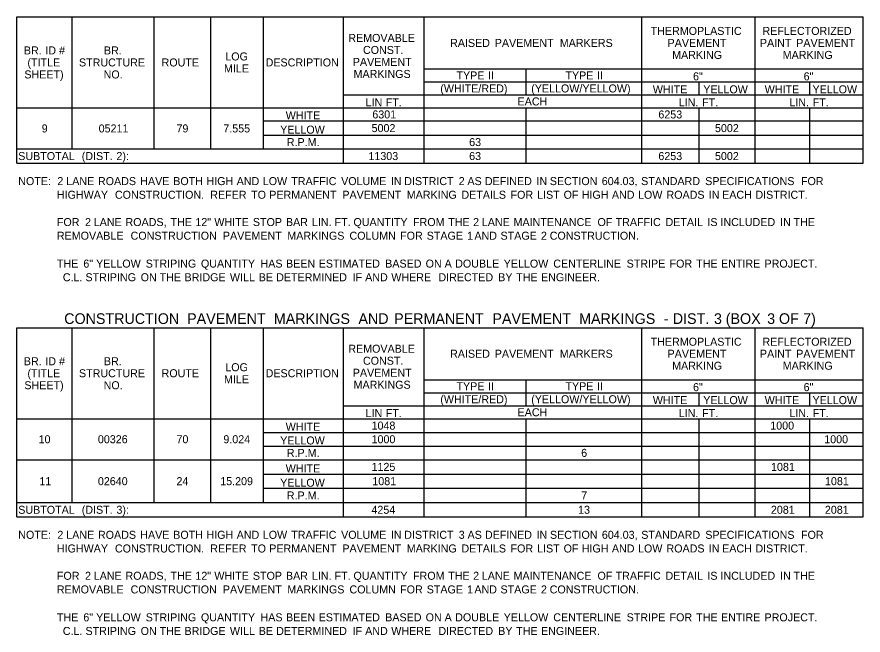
# Model space of a CAD drawing. Extents: x 544255 to 1930787, y -1947044 to 596640.
# Drawn here: x 544255 to 544890, y -1946993 to -1946529 of the extents above; entities that cross this region are included whole.
import ezdxf

# ---------------------------------------------------------------- set-up
doc = ezdxf.new("R2010")
doc.units = 0
doc.layers.add('Default', color=7, linetype='Continuous')

msp = doc.modelspace()

# ---------------------------------------------------------------- linework, layer by layer
at = {"layer": 'Default'}
for p, q in [((544255.45, -1946529.42), (544889.69, -1946529.42)), ((544255.45, -1946529.42), (544560.63, -1946529.42)), ((544255.45, -1946639.1), (544255.45, -1946529.42)), ((544296.89, -1946628.38), (544296.89, -1946529.42)), ((544358.31, -1946628.38), (544358.31, -1946529.42)), ((544400.73, -1946628.38), (544400.73, -1946529.42)), ((544440.21, -1946628.38), (544440.21, -1946529.42)), ((544500.18, -1946639.1), (544500.18, -1946529.42)), ((544560.63, -1946639.1), (544560.63, -1946529.42)), ((544723.94, -1946639.1), (544723.94, -1946529.42)), ((544808.76, -1946597.67), (544808.76, -1946529.42)), ((544808.76, -1946639.1), (544808.76, -1946529.42)), ((544889.69, -1946639.1), (544889.69, -1946529.42)), ((544560.63, -1946568.42), (544889.69, -1946568.42)), ((544637.16, -1946587.92), (544637.16, -1946568.42)), ((544560.63, -1946578.17), (544889.69, -1946578.17)), ((544766.84, -1946587.92), (544766.84, -1946578.17)), ((544849.71, -1946587.92), (544849.71, -1946578.17)), ((544500.18, -1946587.92), (544889.69, -1946587.92)), ((544500.18, -1946597.67), (544500.18, -1946587.92)), ((544255.45, -1946597.67), (544440.21, -1946597.67)), ((544255.45, -1946597.67), (544400.73, -1946597.67)), ((544400.73, -1946597.67), (544889.69, -1946597.67)), ((544637.16, -1946639.1), (544637.16, -1946597.67)), ((544723.94, -1946597.67), (544808.76, -1946597.67)), ((544766.84, -1946639.1), (544766.84, -1946597.67)), ((544808.76, -1946597.67), (544889.69, -1946597.67)), ((544849.71, -1946639.1), (544849.71, -1946597.67)), ((544440.21, -1946607.42), (544889.69, -1946607.42)), ((544440.21, -1946618.14), (544889.69, -1946618.14)), ((544255.45, -1946628.38), (544889.69, -1946628.38)), ((544500.18, -1946639.1), (544500.18, -1946628.38)), ((544255.45, -1946639.1), (544889.69, -1946639.1)), ((544255.45, -1946762.44), (544889.69, -1946762.44)), ((544255.45, -1946762.44), (544560.63, -1946762.44)), ((544255.45, -1946904.3), (544255.45, -1946762.44)), ((544296.89, -1946893.58), (544296.89, -1946762.44)), ((544358.31, -1946893.58), (544358.31, -1946762.44)), ((544400.73, -1946893.58), (544400.73, -1946762.44)), ((544440.21, -1946893.58), (544440.21, -1946762.44)), ((544500.18, -1946904.3), (544500.18, -1946762.44)), ((544560.63, -1946904.3), (544560.63, -1946762.44)), ((544723.94, -1946904.3), (544723.94, -1946762.44)), ((544808.76, -1946830.69), (544808.76, -1946762.44)), ((544808.76, -1946904.3), (544808.76, -1946762.44)), ((544889.69, -1946904.3), (544889.69, -1946762.44)), ((544560.63, -1946801.44), (544889.69, -1946801.44)), ((544637.16, -1946820.94), (544637.16, -1946801.44)), ((544560.63, -1946811.19), (544889.69, -1946811.19)), ((544766.84, -1946820.94), (544766.84, -1946811.19)), ((544849.71, -1946820.94), (544849.71, -1946811.19)), ((544500.18, -1946820.94), (544889.69, -1946820.94)), ((544500.18, -1946830.69), (544500.18, -1946820.94)), ((544255.45, -1946830.69), (544440.21, -1946830.69)), ((544255.45, -1946830.69), (544400.73, -1946830.69)), ((544400.73, -1946830.69), (544889.69, -1946830.69)), ((544637.16, -1946904.3), (544637.16, -1946830.69)), ((544723.94, -1946830.69), (544808.76, -1946830.69)), ((544766.84, -1946904.3), (544766.84, -1946830.69)), ((544808.76, -1946830.69), (544889.69, -1946830.69)), ((544849.71, -1946904.3), (544849.71, -1946830.69)), ((544440.21, -1946840.93), (544889.69, -1946840.93)), ((544440.21, -1946851.17), (544889.69, -1946851.17)), ((544255.45, -1946861.4), (544889.69, -1946861.4)), ((544440.21, -1946872.13), (544889.69, -1946872.13)), ((544440.21, -1946882.85), (544889.69, -1946882.85)), ((544255.45, -1946893.58), (544889.69, -1946893.58)), ((544500.18, -1946904.3), (544500.18, -1946893.58)), ((544255.45, -1946904.3), (544889.69, -1946904.3))]:
    msp.add_line(p, q, dxfattribs=at)

# ---------------------------------------------------------------- texts
for s, height, p in [('THERMOPLASTIC', 6, (544730.47, -1946542.92)), ('REFLECTORIZED', 6, (544814.27, -1946542.92)), ('REMOVABLE', 6, (544503.83, -1946548.17)), ('RAISED', 6, (544580.13, -1946551.92)), (' PAVEMENT', 6, (544611.39, -1946551.92)), (' MARKERS', 6, (544660.13, -1946551.92)), ('PAVEMENT', 6, (544743.15, -1946551.92)), ('PAINT', 6, (544812.37, -1946551.92)), (' PAVEMENT', 6, (544837.35, -1946551.92)), ('BR.', 6, (544260.65, -1946557.54)), (' ID', 6, (544274.51, -1946557.54)), (' #', 6, (544284.8, -1946557.54)), ('BR.', 6, (544320.67, -1946557.54)), ('LOG', 6, (544411.64, -1946562.04)), ('CONST.', 6, (544514.85, -1946557.17)), ('MARKING', 6, (544746.58, -1946560.92)), ('MARKING', 6, (544829.45, -1946560.92)), ('(TITLE', 6, (544263.34, -1946566.54)), ('STRUCTURE', 6, (544301.96, -1946566.54)), ('ROUTE', 6, (544363.89, -1946566.54)), ('DESCRIPTION', 6, (544441.88, -1946566.54)), ('PAVEMENT', 6, (544507.2, -1946566.17)), ('SHEET)', 6, (544261.02, -1946575.54)), ('NO.', 6, (544320.44, -1946575.54)), ('MILE', 6, (544410.67, -1946571.04)), ('MARKINGS', 6, (544507.79, -1946575.17)), ('TYPE', 6, (544584.93, -1946576.29)), (' II', 6, (544606.42, -1946576.29)), ('TYPE', 6, (544666.59, -1946576.29)), (' II', 6, (544688.07, -1946576.29)), ('6"', 6, (544762.24, -1946576.97)), ('6"', 6, (544845.12, -1946576.97)), ('(WHITE/RED)', 6, (544572.8, -1946586.04)), ('(YELLOW/YELLOW)', 6, (544640.95, -1946586.04)), ('WHITE', 6, (544732.09, -1946586.72)), ('YELLOW', 6, (544769.88, -1946586.72)), ('WHITE', 6, (544815.94, -1946586.72)), ('YELLOW', 6, (544851.78, -1946586.72)), ('LIN', 6, (544516.82, -1946596.47)), (' FT.', 6, (544529.66, -1946596.47)), ('EACH', 6, (544630.73, -1946595.79)), ('LIN.', 6, (544751.56, -1946596.47)), (' FT.', 6, (544766.82, -1946596.47)), ('LIN.', 6, (544834.44, -1946596.47)), (' FT.', 6, (544849.69, -1946596.47)), ('WHITE', 6, (544456.92, -1946606.22)), ('6301', 6, (544521.85, -1946605.54)), ('6253', 6, (544736.26, -1946605.54)), ('9', 6, (544274.03, -1946616.02)), ('05211', 6, (544316.72, -1946616.02)), ('79', 6, (544375.05, -1946616.02)), ('7.555', 6, (544410.15, -1946616.02)), ('YELLOW', 6, (544452.77, -1946616.94)), ('5002', 6, (544521.3, -1946615.78)), ('5002', 6, (544778.7, -1946615.78)), ('R.P.M.', 6, (544457.75, -1946626.26)), ('63', 6, (544594.43, -1946626.26)), ('SUBTOTAL', 6, (544256.43, -1946636.74)), (' (DIST.', 6, (544301.82, -1946636.74)), (' 2):', 6, (544327.79, -1946636.74)), ('11303', 6, (544518.93, -1946636.74)), ('63', 6, (544594.42, -1946636.74)), ('6253', 6, (544736.25, -1946636.74)), ('5002', 6, (544778.69, -1946636.74)), ('NOTE:', 6, (544256.43, -1946655.51)), ('  2', 6, (544281.31, -1946655.51)), (' LANE', 6, (544290.19, -1946655.51)), (' ROADS', 6, (544313.97, -1946655.51)), (' HAVE', 6, (544345.67, -1946655.51)), (' BOTH', 6, (544370.39, -1946655.51)), (' HIGH', 6, (544395.33, -1946655.51)), (' AND', 6, (544417.94, -1946655.51)), (' LOW', 6, (544437.52, -1946655.51)), (' TRAFFIC', 6, (544458.84, -1946655.51)), (' VOLUME', 6, (544496.24, -1946655.51)), (' IN', 6, (544533.52, -1946655.51)), (' DISTRICT', 6, (544543.54, -1946655.51)), (' 2', 6, (544584.36, -1946655.51)), (' AS', 6, (544590.9, -1946655.51)), (' DEFINED', 6, (544603.98, -1946655.51)), (' IN', 6, (544642.66, -1946655.51)), (' SECTION', 6, (544652.68, -1946655.51)), (' 604.03,', 6, (544691.59, -1946655.51)), (' STANDARD', 6, (544721.13, -1946655.51)), (' SPECIFICATIONS', 6, (544769.13, -1946655.51)), (' FOR', 6, (544840.9, -1946655.51)), ('             HIGHWAY', 6, (544256.43, -1946665.75)), (' CONSTRUCTION.', 6, (544326.68, -1946665.75)), (' REFER', 6, (544398.14, -1946665.75)), (' TO', 6, (544428.77, -1946665.75)), (' PERMANENT', 6, (544442.37, -1946665.75)), (' PAVEMENT', 6, (544497.17, -1946665.75)), (' MARKING', 6, (544545.45, -1946665.75)), (' DETAILS', 6, (544586.38, -1946665.75)), (' FOR', 6, (544623.21, -1946665.75)), (' LIST', 6, (544643.13, -1946665.75)), (' OF', 6, (544662.99, -1946665.75)), (' HIGH', 6, (544676.57, -1946665.75)), (' AND', 6, (544699.18, -1946665.75)), (' LOW', 6, (544718.77, -1946665.75)), (' ROADS', 6, (544740.09, -1946665.75)), (' IN', 6, (544771.8, -1946665.75)), (' EACH', 6, (544781.82, -1946665.75)), (' DISTRICT.', 6, (544806.77, -1946665.75)), ('             FOR', 6, (544256.43, -1946686.22)), (' 2', 6, (544304.27, -1946686.22)), (' LANE', 6, (544310.82, -1946686.22)), (' ROADS,', 6, (544334.6, -1946686.22)), (' THE', 6, (544368.32, -1946686.22)), (' 12"', 6, (544386.97, -1946686.22)), (' WHITE', 6, (544401.2, -1946686.22)), (' STOP', 6, (544430.09, -1946686.22)), (' BAR', 6, (544454.88, -1946686.22)), (' LIN.', 6, (544474.34, -1946686.22)), (' FT.', 6, (544491.31, -1946686.22)), (' QUANTITY', 6, (544505.47, -1946686.22)), (' FROM', 6, (544550.13, -1946686.22)), (' THE', 6, (544576.5, -1946686.22)), (' 2', 6, (544595.15, -1946686.22)), (' LANE', 6, (544601.7, -1946686.22)), (' MAINTENANCE', 6, (544625.48, -1946686.22)), (' OF', 6, (544688.38, -1946686.22)), (' TRAFFIC', 6, (544701.97, -1946686.22)), (' DETAIL', 6, (544739.36, -1946686.22)), (' IS', 6, (544770.74, -1946686.22)), (' INCLUDED', 6, (544780.55, -1946686.22)), (' IN', 6, (544825.28, -1946686.22)), (' THE', 6, (544835.31, -1946686.22)), ('             REMOVABLE', 6, (544256.43, -1946696.46)), (' CONSTRUCTION', 6, (544338.42, -1946696.46)), (' PAVEMENT', 6, (544407.6, -1946696.46)), (' MARKINGS', 6, (544455.89, -1946696.46)), (' COLUMN', 6, (544502.5, -1946696.46)), (' FOR', 6, (544540.47, -1946696.46)), (' STAGE', 6, (544560.38, -1946696.46)), (' 1', 6, (544590.68, -1946696.46)), (' AND', 6, (544596.13, -1946696.46)), (' STAGE', 6, (544615.71, -1946696.46)), (' 2', 6, (544646.01, -1946696.46)), (' CONSTRUCTION.', 6, (544652.56, -1946696.46)), ('             THE', 6, (544256.43, -1946717.37)), (' 6"', 6, (544303.01, -1946717.37)), (' YELLOW', 6, (544312.58, -1946717.37)), (' STRIPING', 6, (544349.75, -1946717.37)), (' QUANTITY', 6, (544391.15, -1946717.37)), (' HAS', 6, (544435.8, -1946717.37)), (' BEEN', 6, (544454.93, -1946717.37)), (' ESTIMATED', 6, (544479.41, -1946717.37)), (' BASED', 6, (544529.27, -1946717.37)), (' ON', 6, (544559.57, -1946717.37)), (' A', 6, (544573.79, -1946717.37)), (' DOUBLE', 6, (544581.73, -1946717.37)), (' YELLOW', 6, (544618.08, -1946717.37)), (' CENTERLINE', 6, (544655.25, -1946717.37)), (' STRIPE', 6, (544710.24, -1946717.37)), (' FOR', 6, (544742.4, -1946717.37)), (' THE', 6, (544762.32, -1946717.37)), (' ENTIRE', 6, (544780.97, -1946717.37)), (' PROJECT.', 6, (544813.59, -1946717.37)), (' C.L.', 6, (544287.63, -1946727.6)), (' STRIPING', 6, (544304.59, -1946727.6)), (' ON', 6, (544345.99, -1946727.6)), (' THE', 6, (544360.21, -1946727.6)), (' BRIDGE', 6, (544378.86, -1946727.6)), (' WILL', 6, (544412.88, -1946727.6)), (' BE', 6, (544434.47, -1946727.6)), (' DETERMINED', 6, (544447.54, -1946727.6)), (' IF', 6, (544504.85, -1946727.6)), (' AND', 6, (544514.24, -1946727.6)), (' WHERE', 6, (544533.82, -1946727.6)), ('  DIRECTED', 6, (544566.91, -1946727.6)), (' BY', 6, (544613.97, -1946727.6)), (' THE', 6, (544627.42, -1946727.6)), (' ENGINEER.', 6, (544646.07, -1946727.6)), ('CONSTRUCTION', 8, (544290.91, -1946759.62)), (' PAVEMENT', 8, (544380.06, -1946759.62)), (' MARKINGS', 8, (544445.05, -1946759.62)), (' AND', 8, (544508.46, -1946759.62)), (' PERMANENT', 8, (544535.23, -1946759.62)), (' PAVEMENT', 8, (544608.91, -1946759.62)), (' MARKINGS', 8, (544673.9, -1946759.62)), (' DIST.', 8, (544744.06, -1946759.62)), (' 3', 8, (544774.96, -1946759.62)), (' (BOX', 8, (544783.79, -1946759.62)), (' 3', 8, (544814.83, -1946759.62)), (' OF', 8, (544823.67, -1946759.62)), (' 7)', 8, (544841.78, -1946759.62)), (' -', 8, (544737.31, -1946759.62)), ('THERMOPLASTIC', 6, (544730.47, -1946775.94)), ('REFLECTORIZED', 6, (544814.27, -1946775.94)), ('REMOVABLE', 6, (544503.83, -1946781.19)), ('RAISED', 6, (544580.13, -1946784.94)), (' PAVEMENT', 6, (544611.39, -1946784.94)), (' MARKERS', 6, (544660.13, -1946784.94)), ('PAVEMENT', 6, (544743.15, -1946784.94)), ('PAINT', 6, (544812.37, -1946784.94)), (' PAVEMENT', 6, (544837.35, -1946784.94)), ('BR.', 6, (544260.65, -1946790.57)), (' ID', 6, (544274.51, -1946790.57)), (' #', 6, (544284.8, -1946790.57)), ('BR.', 6, (544320.67, -1946790.57)), ('CONST.', 6, (544514.85, -1946790.19)), ('LOG', 6, (544411.64, -1946795.07)), ('MARKING', 6, (544746.58, -1946793.94)), ('MARKING', 6, (544829.45, -1946793.94)), ('(TITLE', 6, (544263.34, -1946799.57)), ('STRUCTURE', 6, (544301.96, -1946799.57)), ('ROUTE', 6, (544363.89, -1946799.57)), ('MILE', 6, (544410.67, -1946804.07)), ('DESCRIPTION', 6, (544441.88, -1946799.57)), ('PAVEMENT', 6, (544507.2, -1946799.19)), ('SHEET)', 6, (544261.02, -1946808.57)), ('NO.', 6, (544320.44, -1946808.57)), ('MARKINGS', 6, (544507.79, -1946808.19)), ('TYPE', 6, (544584.93, -1946809.32)), (' II', 6, (544606.42, -1946809.32)), ('TYPE', 6, (544666.59, -1946809.32)), (' II', 6, (544688.07, -1946809.32)), ('6"', 6, (544762.24, -1946809.99)), ('6"', 6, (544845.12, -1946809.99)), ('(WHITE/RED)', 6, (544572.8, -1946819.07)), ('(YELLOW/YELLOW)', 6, (544640.95, -1946819.07)), ('WHITE', 6, (544732.09, -1946819.74)), ('YELLOW', 6, (544769.88, -1946819.74)), ('WHITE', 6, (544815.94, -1946819.74)), ('YELLOW', 6, (544851.78, -1946819.74)), ('LIN', 6, (544516.82, -1946829.49)), (' FT.', 6, (544529.66, -1946829.49)), ('EACH', 6, (544630.73, -1946828.82)), ('LIN.', 6, (544751.56, -1946829.49)), (' FT.', 6, (544766.82, -1946829.49)), ('LIN.', 6, (544834.44, -1946829.49)), (' FT.', 6, (544849.69, -1946829.49)), ('WHITE', 6, (544456.92, -1946839.73)), ('1048', 6, (544521.27, -1946838.81)), ('1000', 6, (544820.12, -1946838.81)), ('10', 6, (544271.71, -1946849.05)), ('00326', 6, (544316.14, -1946849.05)), ('70', 6, (544375.06, -1946849.05)), ('9.024', 6, (544410.19, -1946849.05)), ('YELLOW', 6, (544452.77, -1946849.97)), ('1000', 6, (544521.28, -1946849.05)), ('1000', 6, (544860.58, -1946849.05)), ('R.P.M.', 6, (544457.75, -1946859.28)), ('6', 6, (544678.41, -1946859.28)), ('WHITE', 6, (544456.92, -1946870.93)), ('1125', 6, (544521.25, -1946869.77)), ('1081', 6, (544820.69, -1946869.77)), ('02640', 6, (544316.15, -1946880.49)), ('24', 6, (544375.06, -1946880.49)), ('15.209', 6, (544407.84, -1946880.49)), ('1081', 6, (544521.85, -1946880.49)), ('1081', 6, (544861.15, -1946880.49)), ('11', 6, (544272.28, -1946880.49)), ('YELLOW', 6, (544452.77, -1946881.65)), ('R.P.M.', 6, (544457.75, -1946891.22)), ('7', 6, (544678.41, -1946891.22)), ('SUBTOTAL', 6, (544256.43, -1946901.94)), (' (DIST.', 6, (544301.82, -1946901.94)), (' 3):', 6, (544327.79, -1946901.94)), ('4254', 6, (544521.18, -1946901.94)), ('13', 6, (544676.07, -1946901.94)), ('2081', 6, (544820.6, -1946901.94)), ('2081', 6, (544861.06, -1946901.94)), ('NOTE:', 6, (544256.43, -1946920.71)), ('  2', 6, (544281.31, -1946920.71)), (' LANE', 6, (544290.19, -1946920.71)), (' ROADS', 6, (544313.97, -1946920.71)), (' HAVE', 6, (544345.67, -1946920.71)), (' BOTH', 6, (544370.39, -1946920.71)), (' HIGH', 6, (544395.33, -1946920.71)), (' AND', 6, (544417.94, -1946920.71)), (' LOW', 6, (544437.52, -1946920.71)), (' TRAFFIC', 6, (544458.84, -1946920.71)), (' VOLUME', 6, (544496.24, -1946920.71)), (' IN', 6, (544533.52, -1946920.71)), (' DISTRICT', 6, (544543.54, -1946920.71)), (' 3', 6, (544584.36, -1946920.71)), (' AS', 6, (544590.97, -1946920.71)), (' DEFINED', 6, (544604.04, -1946920.71)), (' IN', 6, (544642.72, -1946920.71)), (' SECTION', 6, (544652.75, -1946920.71)), (' 604.03,', 6, (544691.66, -1946920.71)), (' STANDARD', 6, (544721.19, -1946920.71)), (' SPECIFICATIONS', 6, (544769.19, -1946920.71)), (' FOR', 6, (544840.96, -1946920.71)), ('             HIGHWAY', 6, (544256.43, -1946930.95)), (' CONSTRUCTION.', 6, (544326.68, -1946930.95)), (' REFER', 6, (544398.14, -1946930.95)), (' TO', 6, (544428.77, -1946930.95)), (' PERMANENT', 6, (544442.37, -1946930.95)), (' PAVEMENT', 6, (544497.17, -1946930.95)), (' MARKING', 6, (544545.45, -1946930.95)), (' DETAILS', 6, (544586.38, -1946930.95)), (' FOR', 6, (544623.21, -1946930.95)), (' LIST', 6, (544643.13, -1946930.95)), (' OF', 6, (544662.99, -1946930.95)), (' HIGH', 6, (544676.57, -1946930.95)), (' AND', 6, (544699.18, -1946930.95)), (' LOW', 6, (544718.77, -1946930.95)), (' ROADS', 6, (544740.09, -1946930.95)), (' IN', 6, (544771.8, -1946930.95)), (' EACH', 6, (544781.82, -1946930.95)), (' DISTRICT.', 6, (544806.77, -1946930.95)), ('             FOR', 6, (544256.43, -1946951.42)), (' 2', 6, (544304.27, -1946951.42)), (' LANE', 6, (544310.82, -1946951.42)), (' ROADS,', 6, (544334.6, -1946951.42)), (' THE', 6, (544368.32, -1946951.42)), (' 12"', 6, (544386.97, -1946951.42)), (' WHITE', 6, (544401.2, -1946951.42)), (' STOP', 6, (544430.09, -1946951.42)), (' BAR', 6, (544454.88, -1946951.42)), (' LIN.', 6, (544474.34, -1946951.42)), (' FT.', 6, (544491.31, -1946951.42)), (' QUANTITY', 6, (544505.47, -1946951.42)), (' FROM', 6, (544550.13, -1946951.42)), (' THE', 6, (544576.5, -1946951.42)), (' 2', 6, (544595.15, -1946951.42)), (' LANE', 6, (544601.7, -1946951.42)), (' MAINTENANCE', 6, (544625.48, -1946951.42)), (' OF', 6, (544688.38, -1946951.42)), (' TRAFFIC', 6, (544701.97, -1946951.42)), (' DETAIL', 6, (544739.36, -1946951.42)), (' IS', 6, (544770.74, -1946951.42)), (' INCLUDED', 6, (544780.55, -1946951.42)), (' IN', 6, (544825.28, -1946951.42)), (' THE', 6, (544835.31, -1946951.42)), ('             REMOVABLE', 6, (544256.43, -1946961.66)), (' CONSTRUCTION', 6, (544338.42, -1946961.66)), (' PAVEMENT', 6, (544407.6, -1946961.66)), (' MARKINGS', 6, (544455.89, -1946961.66)), (' COLUMN', 6, (544502.5, -1946961.66)), (' FOR', 6, (544540.47, -1946961.66)), (' STAGE', 6, (544560.38, -1946961.66)), (' 1', 6, (544590.68, -1946961.66)), (' AND', 6, (544596.13, -1946961.66)), (' STAGE', 6, (544615.71, -1946961.66)), (' 2', 6, (544646.01, -1946961.66)), (' CONSTRUCTION.', 6, (544652.56, -1946961.66)), ('             THE', 6, (544256.43, -1946982.57)), (' 6"', 6, (544303.01, -1946982.57)), (' YELLOW', 6, (544312.58, -1946982.57)), (' STRIPING', 6, (544349.75, -1946982.57)), (' QUANTITY', 6, (544391.15, -1946982.57)), (' HAS', 6, (544435.8, -1946982.57)), (' BEEN', 6, (544454.93, -1946982.57)), (' ESTIMATED', 6, (544479.41, -1946982.57)), (' BASED', 6, (544529.27, -1946982.57)), (' ON', 6, (544559.57, -1946982.57)), (' A', 6, (544573.79, -1946982.57)), (' DOUBLE', 6, (544581.73, -1946982.57)), (' YELLOW', 6, (544618.08, -1946982.57)), (' CENTERLINE', 6, (544655.25, -1946982.57)), (' STRIPE', 6, (544710.24, -1946982.57)), (' FOR', 6, (544742.4, -1946982.57)), (' THE', 6, (544762.32, -1946982.57)), (' ENTIRE', 6, (544780.97, -1946982.57)), (' PROJECT.', 6, (544813.59, -1946982.57)), (' C.L.', 6, (544287.63, -1946992.8)), (' STRIPING', 6, (544304.59, -1946992.8)), (' ON', 6, (544345.99, -1946992.8)), (' THE', 6, (544360.21, -1946992.8)), (' BRIDGE', 6, (544378.86, -1946992.8)), (' WILL', 6, (544412.88, -1946992.8)), (' BE', 6, (544434.47, -1946992.8)), (' DETERMINED', 6, (544447.54, -1946992.8)), (' IF', 6, (544504.85, -1946992.8)), (' AND', 6, (544514.24, -1946992.8)), (' WHERE', 6, (544533.82, -1946992.8)), ('  DIRECTED', 6, (544566.91, -1946992.8)), (' BY', 6, (544613.97, -1946992.8)), (' THE', 6, (544627.42, -1946992.8)), (' ENGINEER.', 6, (544646.07, -1946992.8))]:
    msp.add_text(s, height=height, dxfattribs=at).set_placement(p)

doc.saveas('drawing.dxf')
